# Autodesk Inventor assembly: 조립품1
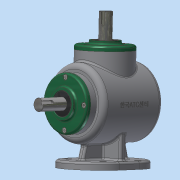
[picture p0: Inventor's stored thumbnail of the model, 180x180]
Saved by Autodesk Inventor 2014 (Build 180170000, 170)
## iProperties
Created: 2023-01
Part Number: 조립품1
Document SubType Name: Assembly
Designer: dg
Author: dg
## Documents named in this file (14)
- C:\Users\dg\Desktop\새 폴더\조립품1.iam
- C:\Users\dg\Desktop\새 폴더\본체.ipt
- C:\Users\dg\Desktop\새 폴더\메인 베벨기어.ipt
- C:\Users\dg\Desktop\새 폴더\메인 축.ipt
- 메인 축.ipt
- C:\Users\dg\Desktop\새 폴더\서브 베벨기어.ipt
- C:\Users\dg\Desktop\새 폴더\서브 축.ipt
- 서브 축.ipt
- C:\Users\dg\Desktop\새 폴더\키 4x4.ipt
- C:\Users\dg\Desktop\새 폴더\키 5x5.ipt
- C:\Users\dg\Desktop\새 폴더\베어링 6203.ipt
- C:\Users\dg\Desktop\새 폴더\커버.ipt
- C:\Users\dg\Desktop\새 폴더\오일실 17 32 8.ipt
- C:\Users\dg\Desktop\새 폴더\M4.ipt
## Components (8 placed, 1 different names)
1. M4:1
2. M4:3
3. M4:4
4. M4:5
5. M4:2
6. M4:6
7. M4:7
8. M4:8
